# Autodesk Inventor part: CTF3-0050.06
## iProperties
Shininess: 64.0
Length Units: 11269
Angle Units: 11279
Time Units: 11290
Mass Units: 11283
Length Display Precision: 3
Angle Display Precision: 2
Compacted: True
Part Number: CTF3-0050.06
Document SubType Name: Modeling
Created: 2003-11
Designer: Lollo
Density: 0.0
Volumn: 0.0
Area: 0.0
PropertySet Name: Model Information
Control State: 0
Master: False
Checked Out: False
Author: Lollo
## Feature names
1. Estrusione1 [Extrusion]
2. Foro5 [Hole]
